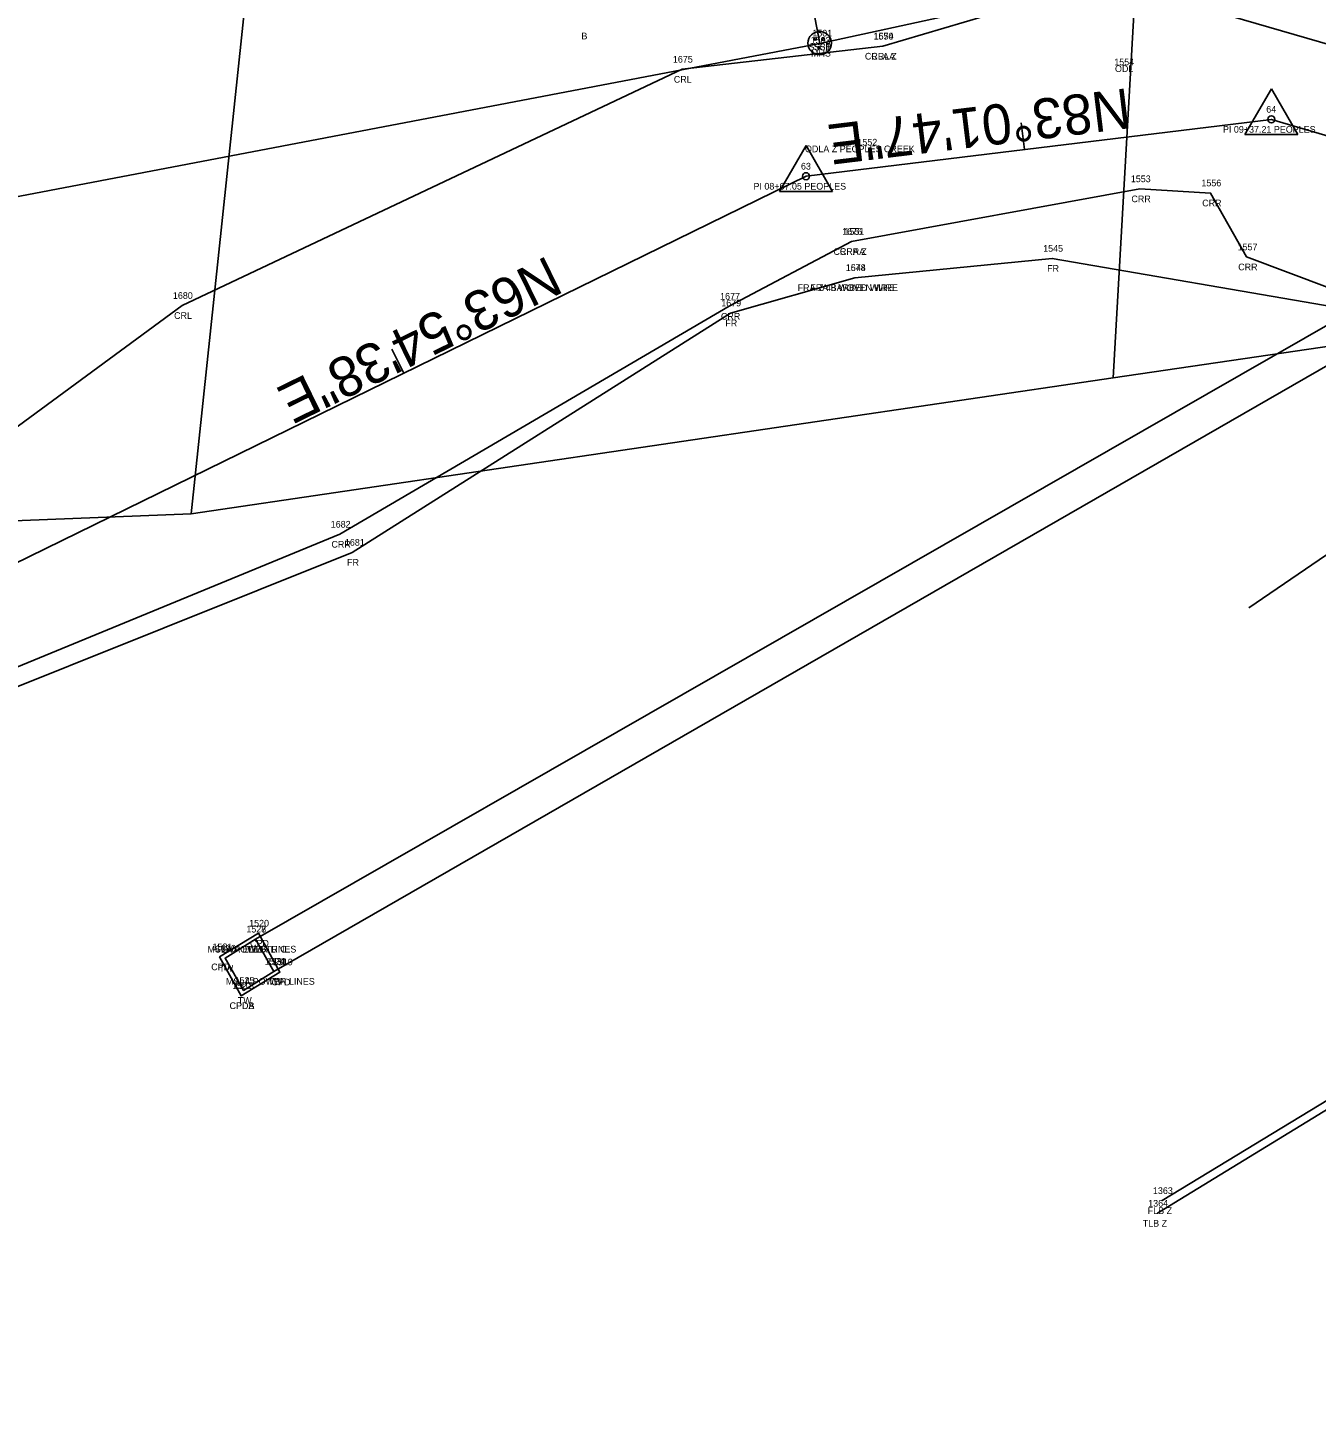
# Model space of a CAD drawing. Extents: x 1812113 to 1819860, y 1177395 to 1181185.
# Drawn here: x 1813371.7 to 1813564.5, y 1178500.8 to 1178709.1 of the extents above; entities that cross this region are included whole.
import ezdxf

# ---------------------------------------------------------------- set-up
doc = ezdxf.new("R2010")
doc.units = 0
for name, color, linetype in [('RD_EX_Bldg_txCode', 7, 'Continuous'), ('RD_EX_Conc', 7, 'Continuous'), ('RD_EX_Conc_txCode', 7, 'Continuous'), ('RD_EX_DR_Inlet', 7, 'Continuous'), ('RD_EX_DV_Prop', 7, 'Continuous'), ('RD_EX_Fence_Other', 7, 'Continuous'), ('RD_EX_Fence_Other_txCode', 7, 'Continuous'), ('RD_EX_H2O', 7, 'Continuous'), ('RD_EX_H2O_txCode', 7, 'Continuous'), ('RD_EX_Misc', 7, 'Continuous'), ('RD_EX_Misc_txCode', 7, 'Continuous'), ('RD_EX_UT', 7, 'Continuous'), ('RD_EX_UT_txCode', 7, 'Continuous'), ('RD_EX_VEG', 7, 'Continuous'), ('RD_EX_VEG_txCode', 7, 'Continuous'), ('RD_HC_CL', 7, 'Continuous'), ('RD_HC_Data', 7, 'Continuous'), ('RD_HC_Data_Tic', 7, 'Continuous'), ('RD_HC_txCode', 7, 'Continuous'), ('RD_PD_ALT4_LnLine', 7, 'Continuous'), ('RD_SMD_Locator', 7, 'Continuous')]:
    doc.layers.add(name, color=color, linetype=linetype)

msp = doc.modelspace()

# ---------------------------------------------------------------- linework, layer by layer
at = {"layer": 'RD_EX_Conc'}
msp.add_lwpolyline([(1813403.58, 1178564.28), (1813409.39, 1178567.82), (1813406.16, 1178573.63), (1813400.36, 1178570.09), (1813403.58, 1178564.28)], dxfattribs=at)
at = {"layer": 'RD_EX_DR_Inlet'}
for centre, radius in [((1813490.17, 1178706.82), 1.75), ((1813489.51, 1178707.45), 0.175), ((1813490.73, 1178707.38), 0.175), ((1813490.09, 1178706.16), 0.175)]:
    msp.add_circle(centre, radius, dxfattribs=at)
at = {"layer": 'RD_EX_DV_Prop'}
for p, q in [((1813409.98, 1178767.65), (1813396.08, 1178636.38)), ((1813534.09, 1178656.72), (1813539.17, 1178745.92)), ((1813739.05, 1178686.93), (1813534.09, 1178656.72)), ((1813396.08, 1178636.38), (1813534.09, 1178656.72)), ((1813247.98, 1178630.56), (1813396.08, 1178636.38))]:
    msp.add_line(p, q, dxfattribs=at)
at = {"layer": 'RD_EX_Fence_Other'}
for points in [[(1813495.44, 1178671.73), (1813524.97, 1178674.61), (1813567.3, 1178667.34), (1813625.77, 1178659.53), (1813676.75, 1178657.94), (1813689.16, 1178653.47)], [(1813495.44, 1178671.73), (1813476.81, 1178666.44), (1813420.19, 1178630.62), (1813335.47, 1178596.68), (1813279.97, 1178607.5)], [(1813495.44, 1178671.73), (1813476.81, 1178666.44), (1813420.19, 1178630.62), (1813335.47, 1178596.68), (1813279.97, 1178607.5)], [(1813689.16, 1178653.47), (1813706.15, 1178633.63), (1813541.42, 1178533.61)]]:
    msp.add_lwpolyline(points, dxfattribs=at)
at = {"layer": 'RD_EX_H2O'}
for points in [[(1813499.62, 1178706.37), (1813533.11, 1178716.31), (1813566.87, 1178706.45), (1813581.02, 1178703.79), (1813602.73, 1178697.66), (1813630.18, 1178688.94), (1813658.74, 1178690.22), (1813683.52, 1178690.56), (1813733.77, 1178695.63), (1813767.86, 1178725.16), (1813778.94, 1178729.95)], [(1813499.62, 1178706.37), (1813469.57, 1178702.91), (1813394.78, 1178667.56), (1813339.87, 1178627.25), (1813279.53, 1178636.34)], [(1813499.62, 1178706.37), (1813469.57, 1178702.91), (1813394.78, 1178667.56), (1813339.87, 1178627.25), (1813279.53, 1178636.34)], [(1813494.93, 1178677.14), (1813538.08, 1178685.02), (1813548.67, 1178684.4), (1813554.06, 1178674.83), (1813572.78, 1178667.8), (1813599.8, 1178663.18), (1813623.26, 1178662.12), (1813655.35, 1178662.6), (1813687.65, 1178668.53), (1813720.68, 1178667.78), (1813740.16, 1178669.89), (1813749.02, 1178672.08), (1813765.42, 1178660.89)], [(1813494.93, 1178677.14), (1813476.64, 1178667.45), (1813418.36, 1178633.33), (1813336.03, 1178599.49), (1813281.53, 1178610.55)], [(1813494.93, 1178677.14), (1813476.64, 1178667.45), (1813418.36, 1178633.33), (1813336.03, 1178599.49), (1813281.53, 1178610.55)]]:
    msp.add_lwpolyline(points, dxfattribs=at)
at = {"layer": 'RD_EX_Misc'}
for points in [[(1813405.71, 1178572.74), (1813779.17, 1178786.7), (1813799.35, 1179222.21)], [(1813408.47, 1178567.92), (1813786.33, 1178785.29), (1813804.76, 1179221.83)]]:
    msp.add_lwpolyline(points, dxfattribs=at)
at = {"layer": 'RD_EX_UT'}
for points in [[(1812996.89, 1178919.95), (1813204.49, 1178832.44), (1813481.3, 1178753.03), (1813490.2, 1178706.76)], [(1813817.45, 1178777.9), (1813490.2, 1178706.76), (1813294.33, 1178669.42)], [(1813405.71, 1178572.74), (1813408.47, 1178567.92), (1813403.94, 1178565.07), (1813401.18, 1178569.89), (1813405.71, 1178572.74)]]:
    msp.add_lwpolyline(points, dxfattribs=at)
at = {"layer": 'RD_EX_VEG'}
msp.add_lwpolyline([(1813569.58, 1178500.76), (1813635.35, 1178535.15), (1813737.8, 1178606.06), (1813775.9, 1178641.25), (1813752.75, 1178672.45), (1813690.46, 1178652.62), (1813708.11, 1178634.09), (1813540.71, 1178531.72)], dxfattribs=at)
at = {"layer": 'RD_HC_CL'}
for p, q in [((1813488.13, 1178686.91), (1813557.77, 1178695.42)), ((1813557.77, 1178695.42), (1813618, 1178677.68)), ((1813337.95, 1178613.37), (1813488.13, 1178686.91))]:
    msp.add_line(p, q, dxfattribs=at)
at = {"layer": 'RD_HC_Data'}
for p, q in [((1813553.8, 1178693.13), (1813557.77, 1178700.01)), ((1813557.77, 1178700.01), (1813561.74, 1178693.13)), ((1813553.8, 1178693.13), (1813561.74, 1178693.13)), ((1813484.16, 1178684.62), (1813488.13, 1178691.5)), ((1813488.13, 1178691.5), (1813492.1, 1178684.62)), ((1813484.16, 1178684.62), (1813492.1, 1178684.62))]:
    msp.add_line(p, q, dxfattribs=at)
for centre in [(1813557.77, 1178695.42), (1813488.13, 1178686.91)]:
    msp.add_circle(centre, 0.529, dxfattribs=at)
at = {"layer": 'RD_HC_Data_Tic'}
for p, q in [((1813520.83, 1178690.91), (1813520.35, 1178694.88)), ((1813427.91, 1178657.42), (1813426.15, 1178661.01))]:
    msp.add_line(p, q, dxfattribs=at)
at = {"layer": 'RD_PD_ALT4_LnLine'}
msp.add_line((1813554.39, 1178622.31), (1813716.04, 1178732.96), dxfattribs=at)
at = {"layer": 'RD_SMD_Locator'}
for centre in [(1813490.2, 1178706.76), (1813490.2, 1178706.76), (1813499.62, 1178706.37), (1813499.62, 1178706.37), (1813499.62, 1178706.37), (1813535.61, 1178703.5), (1813469.57, 1178702.91), (1813469.57, 1178702.91), (1813557.77, 1178695.42), (1813497.15, 1178691.5), (1813488.13, 1178686.91), (1813538.08, 1178685.02), (1813548.67, 1178684.4), (1813494.93, 1178677.14), (1813494.93, 1178677.14), (1813494.93, 1178677.14), (1813524.97, 1178674.61), (1813554.06, 1178674.83), (1813495.44, 1178671.73), (1813495.44, 1178671.73), (1813495.44, 1178671.73), (1813394.78, 1178667.56), (1813394.78, 1178667.56), (1813476.64, 1178667.45), (1813476.64, 1178667.45), (1813476.81, 1178666.44), (1813476.81, 1178666.44), (1813418.36, 1178633.33), (1813418.36, 1178633.33), (1813420.19, 1178630.62), (1813420.19, 1178630.62), (1813405.71, 1178572.74), (1813405.71, 1178572.74), (1813405.71, 1178572.74), (1813406.16, 1178573.63), (1813400.36, 1178570.09), (1813401.18, 1178569.89), (1813408.47, 1178567.92), (1813408.47, 1178567.92), (1813409.39, 1178567.82), (1813403.58, 1178564.28), (1813403.58, 1178564.28), (1813403.94, 1178565.07), (1813541.42, 1178533.61), (1813540.71, 1178531.72)]:
    msp.add_circle(centre, 0.001, dxfattribs=at)

# ---------------------------------------------------------------- texts
at = {"layer": 'RD_EX_Bldg_txCode'}
msp.add_text('B', height=1, dxfattribs=at).set_placement((1813454.51, 1178707.39))
at = {"layer": 'RD_EX_Conc_txCode'}
for s, p in [('1520', (1813404.78, 1178574.63)), ('1521', (1813399.29, 1178571.09)), ('CPD', (1813404.91, 1178571.63)), ('1519', (1813408.33, 1178568.82)), ('CPD', (1813399.1, 1178568.09)), ('1522', (1813402.24, 1178565.28)), ('1518', (1813402.52, 1178565.28)), ('CPD', (1813408.14, 1178565.82)), ('CPDA', (1813401.84, 1178562.28)), ('CPDB', (1813401.86, 1178562.28))]:
    msp.add_text(s, height=1, dxfattribs=at).set_placement(p)
at = {"layer": 'RD_EX_Fence_Other_txCode'}
for s, p in [('1545', (1813523.62, 1178675.61)), ('1678', (1813494.07, 1178672.73)), ('1678', (1813494.07, 1178672.73)), ('1544', (1813494.1, 1178672.73)), ('FR', (1813524.21, 1178672.61)), ('FRA Z 48 WOVEN WIRE', (1813486.87, 1178669.73)), ('FRA BARBED WIRE', (1813488.77, 1178669.73)), ('FRA BARBED WIRE', (1813488.77, 1178669.73)), ('1679', (1813475.44, 1178667.44)), ('1679', (1813475.44, 1178667.44)), ('FR', (1813476.05, 1178664.44)), ('FR', (1813476.05, 1178664.44)), ('1681', (1813419.11, 1178631.62)), ('1681', (1813419.11, 1178631.62)), ('FR', (1813419.44, 1178628.62)), ('FR', (1813419.44, 1178628.62)), ('1363', (1813540.05, 1178534.61)), ('FLB Z', (1813539.27, 1178531.61))]:
    msp.add_text(s, height=1, dxfattribs=at).set_placement(p)
at = {"layer": 'RD_EX_H2O_txCode'}
for s, p in [('1550', (1813498.23, 1178707.37)), ('1674', (1813498.25, 1178707.37)), ('1674', (1813498.25, 1178707.37)), ('CRLA Z', (1813496.94, 1178704.37)), ('CRLA', (1813497.9, 1178704.37)), ('CRLA', (1813497.9, 1178704.37)), ('1675', (1813468.2, 1178703.91)), ('1675', (1813468.2, 1178703.91)), ('1554', (1813534.26, 1178703.5)), ('ODL', (1813534.37, 1178702.5)), ('CRL', (1813468.34, 1178700.91)), ('CRL', (1813468.34, 1178700.91)), ('ODLA Z PEOPLES CREEK', (1813487.97, 1178690.5)), ('1552', (1813495.81, 1178691.5)), ('1553', (1813536.74, 1178686.02)), ('1556', (1813547.3, 1178685.4)), ('CRR', (1813536.83, 1178683.02)), ('CRR', (1813547.42, 1178682.4)), ('1676', (1813493.54, 1178678.14)), ('1676', (1813493.54, 1178678.14)), ('1551', (1813493.87, 1178678.14)), ('CRRA Z', (1813492.23, 1178675.14)), ('CRRA', (1813493.19, 1178675.14)), ('CRRA', (1813493.19, 1178675.14)), ('1557', (1813552.72, 1178675.83)), ('CRR', (1813552.81, 1178672.83)), ('1680', (1813393.37, 1178668.56)), ('1680', (1813393.37, 1178668.56)), ('1677', (1813475.27, 1178668.45)), ('1677', (1813475.27, 1178668.45)), ('CRL', (1813393.55, 1178665.56)), ('CRL', (1813393.55, 1178665.56)), ('CRR', (1813475.39, 1178665.45)), ('CRR', (1813475.39, 1178665.45)), ('1682', (1813416.99, 1178634.33)), ('1682', (1813416.99, 1178634.33)), ('CRR', (1813417.1, 1178631.33)), ('CRR', (1813417.1, 1178631.33))]:
    msp.add_text(s, height=1, dxfattribs=at).set_placement(p)
at = {"layer": 'RD_EX_Misc_txCode'}
for s, p in [('1528', (1813404.36, 1178573.74)), ('MSLA POWER LINES', (1813398.54, 1178570.74)), ('1531', (1813407.4, 1178568.92)), ('MSLA POWER LINES', (1813401.3, 1178565.92))]:
    msp.add_text(s, height=1, dxfattribs=at).set_placement(p)
at = {"layer": 'RD_EX_UT_txCode'}
for s, p in [('1502', (1813488.82, 1178706.76)), ('1503', (1813488.82, 1178706.76)), ('1501', (1813489.07, 1178707.82)), ('SS3B', (1813488.5, 1178705.76)), ('MHS', (1813488.88, 1178704.82)), ('SS1', (1813489.26, 1178705.76)), ('1523', (1813404.36, 1178573.74)), ('1527', (1813404.36, 1178573.74)), ('1526', (1813399.81, 1178570.89)), ('TWA ELECTRIC', (1813400.45, 1178570.74)), ('TWB', (1813404.37, 1178570.74)), ('1524', (1813407.12, 1178568.92)), ('TW', (1813400.32, 1178567.89)), ('1525', (1813402.6, 1178566.07)), ('TW', (1813407.61, 1178565.92)), ('TW', (1813403.08, 1178563.07))]:
    msp.add_text(s, height=1, dxfattribs=at).set_placement(p)
at = {"layer": 'RD_EX_VEG_txCode'}
for s, p in [('1364', (1813539.34, 1178532.72)), ('TLB Z', (1813538.52, 1178529.72))]:
    msp.add_text(s, height=1, dxfattribs=at).set_placement(p)
at = {"layer": 'RD_HC_Data'}
for s, rotation, p in [('N83%%d01\'47"E', 186.9704, (1813536.31, 1178700.1)), ('N63%%d54\'38"E', 206.0895, (1813449.47, 1178675.1))]:
    msp.add_text(s, height=6, rotation=rotation, dxfattribs=at).set_placement(p)
at = {"layer": 'RD_HC_txCode'}
for s, p in [('64', (1813557.01, 1178696.42)), ('PI 09+37.21 PEOPLES', (1813550.53, 1178693.42)), ('63', (1813487.37, 1178687.91)), ('PI 08+67.05 PEOPLES', (1813480.26, 1178684.91))]:
    msp.add_text(s, height=1, dxfattribs=at).set_placement(p)

doc.saveas('drawing.dxf')
